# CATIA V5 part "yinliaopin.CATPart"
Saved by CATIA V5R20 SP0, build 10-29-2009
Part number: LFZJ
Material "Dark orange"
Material "Dark orange"
Bounding box of the stored display mesh (mm): x -35 to 35, y -35 to 35, z -70 to 65
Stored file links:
  C:\Users\LFZJ1125\Desktop\yinliaopin.CATPart
  D:\catiaM\win_b64\startup\materials\Catalog.CATMaterial
  D:\catiaM\win_b64\startup\materials\Advanced_Materials.CATMaterial
  D:\catiaM\win_b64\startup\materials\shaders\CATIA_Environment_2DMap_Street_2048.dds
  D:\catiaM\win_b64\startup\materials\shaders\CATIA_Normal_2DMap_Scratches_1024.dds
  D:\catiaM\win_b64\startup\materials\shaders\CATIA_Metal_Brushed.cgfx
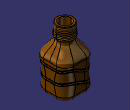
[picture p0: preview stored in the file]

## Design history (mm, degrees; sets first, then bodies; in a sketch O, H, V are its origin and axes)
Set1
  Sketch1 on xy-plane, origin (0, 0, 0), H (1, 0, 0), V (0, 1, 0)
    line L1 (35, 35) -> (35, -35)
    line L2 (35, -35) -> (-35, -35)
    line L3 (-35, -35) -> (-35, 35)
    line L4 (-35, 35) -> (35, 35)
    length L4 = 70
    distance L4 L2 = 70
    vertical: L1 V, L3 V
    horizontal: L2 H, L4 H
    equidistance: L1 L3 O, L2 L4 O
  Sketch2 on face of Pad1 from Sketch1.L2, origin (0, -35, 0), H (1, 0, 0), V (0, 0, 1)
    spline S1 through (-70.2081, -27.8564) (-23.6233, -49.1633) (16.2697, -34.7876) (51.7874, -47.623)
  Extrude1: Element1 Sketch2, Lim1 80, Lim2 0
  MultiSel1: CommonCtxFeats ({extract ExtractElem face of Pad1 from Sketch1.L1}; {extract ExtractElem face of Fillet1}; {extract ExtractElem face of Pad1 from Sketch1.L2}; {extract ExtractElem face of Fillet1}; {extract ExtractElem face of Pad1 from Sketch1.L3}; {extract ExtractElem face of Fillet1}; {extract ExtractElem face of Pad1 from Sketch1.L4}; {extract ExtractElem face of Fillet1})
  Join1: Elements ({intersect ToIntersect1 {extract ExtractElem face of Fillet1}, ToIntersect2 Extrude1}; {intersect ToIntersect1 {extract ExtractElem face of Pad1 from Sketch1.L2}, ToIntersect2 Extrude1}; {intersect ToIntersect1 {extract ExtractElem face of Fillet1}, ToIntersect2 Extrude1}; {intersect ToIntersect1 {extract ExtractElem face of Pad1 from Sketch1.L1}, ToIntersect2 Extrude1}; {intersect ToIntersect1 {extract ExtractElem face of Fillet1}, ToIntersect2 Extrude1}; {intersect ToIntersect1 {extract ExtractElem face of Pad1 from Sketch1.L4}, ToIntersect2 Extrude1}; {intersect ToIntersect1 {extract ExtractElem face of Fillet1}, ToIntersect2 Extrude1}; {intersect ToIntersect1 {extract ExtractElem face of Pad1 from Sketch1.L3}, ToIntersect2 Extrude1})
  Point1: type OnCurve, Support Join1, RefPoint vertex [face of MultiSel1 | face of MultiSel1], Length 115.646
  Plane1: type Normal, Curve Join1, RefPoint Point1
  Circle1: type CtrRad, Start 0, End 180, Center Point1, Support Plane1, Radius 2, FirstDirection (0, 1, 0)
  Sketch3 on face of Pad1 from Sketch1.L4, origin (0, 35, 0), H (-1, 0, 0), V (0, 0, 1)
    spline S1 through (-48.9626, -20.4932) (-15.4214, -9.0883) (8.2099, -20.4932) (51.4069, -4.5263)
  Extrude2: Element1 Sketch3, Lim1 80, Lim2 0
  MultiSel2: CommonCtxFeats ({extract ExtractElem face of Pad1 from Sketch1.L4}; {extract ExtractElem face of Fillet1}; {extract ExtractElem face of Pad1 from Sketch1.L1}; {extract ExtractElem face of Fillet1}; {extract ExtractElem face of Pad1 from Sketch1.L2}; {extract ExtractElem face of Fillet1}; {extract ExtractElem face of Pad1 from Sketch1.L3}; {extract ExtractElem face of Fillet1})
  Join2: Elements ({intersect ToIntersect1 {extract ExtractElem face of Pad1 from Sketch1.L2}, ToIntersect2 Extrude2}; {intersect ToIntersect1 {extract ExtractElem face of Fillet1}, ToIntersect2 Extrude2}; {intersect ToIntersect1 {extract ExtractElem face of Pad1 from Sketch1.L3}, ToIntersect2 Extrude2}; {intersect ToIntersect1 {extract ExtractElem face of Fillet1}, ToIntersect2 Extrude2}; {intersect ToIntersect1 {extract ExtractElem face of Pad1 from Sketch1.L4}, ToIntersect2 Extrude2}; {intersect ToIntersect1 {extract ExtractElem face of Fillet1}, ToIntersect2 Extrude2}; {intersect ToIntersect1 {extract ExtractElem face of Pad1 from Sketch1.L1}, ToIntersect2 Extrude2}; {intersect ToIntersect1 {extract ExtractElem face of Fillet1}, ToIntersect2 Extrude2})
  Plane2: type Normal, Curve Join2, RefPoint vertex [face of MultiSel2 | face of MultiSel2]
  Circle2: type CtrRad, Start 0, End 180, Center vertex [face of MultiSel2 | face of MultiSel2], Support Plane2, Radius 2, FirstDirection (0, -1, 0)
Body1 (main body), material "Dark orange"
  Pad1: profile Sketch1, direction (0, 0, -1), length 70
  Fillet1: on edge [face of Pad1 from Sketch1.L4 | face of Pad1 from Sketch1.L3]; edge [face of Pad1 from Sketch1.L1 | face of Pad1 from Sketch1.L4]; edge [face of Pad1 from Sketch1.L3 | face of Pad1 from Sketch1.L2]; edge [face of Pad1 from Sketch1.L2 | face of Pad1 from Sketch1.L1]
  Fillet2: radius 10, on end face of Pad1
  Plane3: type Offset, RefPlane xy-plane, Offset 35
  Sketch4 on Plane3, origin (0, 0, 35), H (1, 0, 0), V (0, 1, 0)
    circle A1 centre (0, 0) radius 17.7599
  Pad2: profile Sketch4, direction (0, 0, 1), length 30
  Sketch5 on xy-plane, origin (0, 0, 0), H (1, 0, 0), V (0, 1, 0)
    point P1 (125.3181, 41.16)
    point P2 (35, 0)
    coincidence: P2 H
  Sketch6 on Plane3, origin (0, 0, 35), H (1, 0, 0), V (0, 1, 0)
    point P1 (17.76, 0)
    distance P1 V = 17.76
    coincidence: P1 H
  Loft1: solid, Sections ({boundary Boundary {extract ExtractElem start face of Pad1}}; {boundary Boundary {extract ExtractElem start face of Pad2}}), StartFace start face of Pad1, EndFace start face of Pad2
  Plane4: type Offset, RefPlane Plane3, Offset 2
  Sketch7 on Plane4, origin (0, 0, 37), H (1, 0, 0), V (0, 1, 0)
    point P1 (17.76, 0)
    distance P1 V = 17.76
    coincidence: P1 H
  Shell1: IntOffset 4, Face end face of Pad2, ExtOffset 0
  Helix1: Direction Z axis, RefPoint Sketch7, Pitch 3, Height 25, TaperAngle 0
  Point2: type OnCurve, Support Helix1, Length 924.932
  Point3: type OnCurve, Support Helix1, Length 924.003
  Line1: type PtDir, RefPoint Sketch7, Direction (1, 0, 0), Start 0, End 10
  Line2: type PtDir, RefPoint vertex of Helix1, Direction (0, 1, 0), Start 0, End 10
  Connect1: Curve1 Line2, Point1 vertex of Line2, Tension1 1, Curve2 Helix1, Point2 Point2, Tension2 1
  Connect2: Curve1 Line1, Point1 vertex of Line1, Tension1 1, Curve2 Connect1, Point2 Point3, Tension2 1
  Plane5: type Normal, Curve Connect2, RefPoint vertex of Connect2
  Circle3: type CtrRad, Start 0, End 180, Center vertex of Connect2, Support Plane5, Radius 2, FirstDirection (0, 1, 0)
  Slot1: profile Circle1, centre curve Join1
  Slot2: profile Circle2, centre curve Join2
  Fillet3: radius 1, on edge [face of Pad1 from Sketch1.L2 | face of Slot2]; edge [face of Slot2 | face of Pad1 from Sketch1.L2]; edge [face of Pad1 from Sketch1.L2 | face of Slot1]; edge [face of Slot1 | face of Pad1 from Sketch1.L2]
Body2, material "Dark orange"
  Rib1: profile Circle3, centre curve Connect2
  Sketch8 on end face of Pad2, origin (0, 0, 65), H (1, 0, 0), V (0, 1, 0)
    circle A1 centre (0, 0) radius 16.1388
  Pocket1: profile Sketch8, direction (0, 0, -1), length 30
Body3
